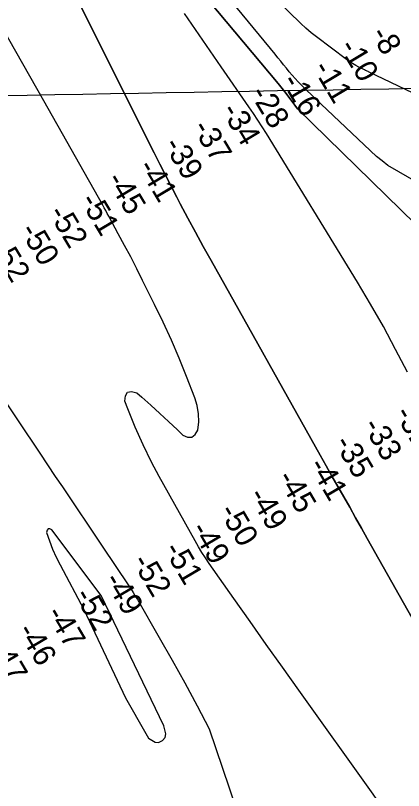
# Model space of a CAD drawing. Extents: x 3914892 to 3953151, y 242587 to 268572.
# Drawn here: x 3938431 to 3939590, y 258411 to 260725 of the extents above; entities that cross this region are included whole.
import ezdxf

# ---------------------------------------------------------------- set-up
doc = ezdxf.new("R2010")
doc.units = 0
for name, color, linetype in [('V-GRID-MAJR', 7, 'Continuous'), ('V-RIVR-RANG', 7, 'Continuous'), ('V-TOPO-DPTH', 7, 'Continuous'), ('V-TOPO-MAJR', 7, 'Continuous'), ('V-TOPO-MINR', 7, 'Continuous')]:
    doc.layers.add(name, color=color, linetype=linetype)

msp = doc.modelspace()

# ---------------------------------------------------------------- linework, layer by layer
at = {"layer": 'V-GRID-MAJR'}
msp.add_spline([(3918942.3880000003, 260140.297), (3924259.416, 260233.496), (3929576.431, 260327.467), (3934893.433, 260422.212), (3940210.42, 260517.73), (3945527.394, 260614.022), (3950844.353, 260711.087), (3950844.3540000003, 260711.087)], degree=3, dxfattribs=at)
at = {"layer": 'V-TOPO-DPTH'}
for points in [[(3937935.6033522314, 262362.5402043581), (3937946.807549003, 262343.63632242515), (3937958.257643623, 262324.87497740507), (3938066.361568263, 262151.54759992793), (3938132.132563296, 262046.2824872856), (3938198.016029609, 261941.08794122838), (3938264.0682028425, 261835.99924504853), (3938330.2328473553, 261730.98111545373), (3938533.302113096, 261409.237278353), (3938543.3552703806, 261393.41452513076), (3938553.4715195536, 261377.63248157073), (3938563.682406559, 261361.91150250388), (3938573.9563854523, 261346.23123309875), (3938689.531013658, 261170.99052217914), (3938725.5086589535, 261118.47567351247), (3938762.682482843, 261066.8546234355), (3938801.6505746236, 261016.5742712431), (3939215.8425195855, 260521.97311348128), (3939235.1154305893, 260496.93985141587), (3939254.337950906, 260471.8680751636), (3939273.484885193, 260446.73852763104), (3939890.5030939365, 259842.8503603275), (3939899.174331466, 259835.0878290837)], [(3937935.6033522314, 262362.5402043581), (3937946.807549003, 262343.63632242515), (3937958.257643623, 262324.87497740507), (3938066.361568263, 262151.54759992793), (3938132.132563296, 262046.2824872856), (3938198.016029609, 261941.08794122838), (3938264.0682028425, 261835.99924504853), (3938330.2328473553, 261730.98111545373), (3938533.302113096, 261409.237278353), (3938543.3552703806, 261393.41452513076), (3938553.4715195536, 261377.63248157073), (3938563.682406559, 261361.91150250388), (3938573.9563854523, 261346.23123309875), (3938689.531013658, 261170.99052217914), (3938725.5086589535, 261118.47567351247), (3938762.682482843, 261066.8546234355), (3938801.6505746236, 261016.5742712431), (3939215.8425195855, 260521.97311348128), (3939235.1154305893, 260496.93985141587), (3939254.337950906, 260471.8680751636), (3939273.484885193, 260446.73852763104), (3939890.5030939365, 259842.8503603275)], [(3940110.2800000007, 260258.01), (3939485.676288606, 260556.6594979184), (3939484.132907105, 260557.4550404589), (3939481.009910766, 260558.97150695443), (3939479.4302959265, 260559.69243090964), (3939476.273892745, 260561.1410262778), (3939473.154218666, 260562.6671138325), (3939456.795925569, 260570.9211261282), (3939447.215830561, 260576.0725193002), (3939437.834092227, 260581.54451440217), (3939428.749888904, 260587.49741239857), (3939419.864042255, 260593.77091232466), (3939329.7874783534, 260660.9505154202), (3939313.6231003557, 260673.72242143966), (3939297.9699429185, 260687.0614582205), (3939283.0836163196, 260701.25119114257), (3938621.524369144, 261346.29575137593)], [(3938618.811265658, 260766.56261342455), (3938669.4139997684, 260666.69985866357), (3938845.1139194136, 260314.8285701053), (3938861.841960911, 260281.58747193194), (3938878.7077570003, 260248.41695782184), (3938895.7801849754, 260215.35231980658), (3938912.9903675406, 260182.35826585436), (3938923.19890059, 260162.93525665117), (3938945.78941881, 260120.3764528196), (3938968.610226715, 260077.94271225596), (3938991.7764691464, 260035.69656659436), (3939015.1730012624, 259993.57548420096), (3939341.304889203, 259412.03733793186), (3939358.7805479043, 259380.94331128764), (3939376.294527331, 259349.87093091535), (3939393.8659878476, 259318.83101995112), (3939411.475769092, 259287.8127552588), (3939429.099378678, 259256.80227260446), (3939446.703105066, 259225.78051958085), (3939464.277006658, 259194.74186100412), (3939481.8310250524, 259163.69193205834), (3939832.9714719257, 258541.88976801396)], [(3939832.9714719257, 258541.88976801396), (3939481.8310250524, 259163.69193205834), (3939464.277006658, 259194.74186100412), (3939446.703105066, 259225.78051958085), (3939429.099378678, 259256.80227260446), (3939411.475769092, 259287.8127552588), (3939393.8659878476, 259318.83101995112), (3939376.294527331, 259349.87093091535), (3939358.7805479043, 259380.94331128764), (3939341.304889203, 259412.03733793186), (3939015.1730012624, 259993.57548420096), (3938991.7764691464, 260035.69656659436), (3938968.610226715, 260077.94271225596), (3938945.78941881, 260120.3764528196), (3938923.19890059, 260162.93525665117), (3938912.9903675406, 260182.35826585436), (3938895.7801849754, 260215.35231980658), (3938878.7077570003, 260248.41695782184), (3938861.841960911, 260281.58747193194), (3938845.1139194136, 260314.8285701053), (3938669.4139997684, 260666.69985866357), (3938618.811265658, 260766.56261342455)], [(3939601.6381155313, 259659.9443888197), (3939566.333453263, 259728.33550029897), (3939529.860262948, 259796.07768271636), (3939491.634280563, 259862.84647154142), (3939452.239770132, 259928.9663313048), (3939180.239102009, 260372.25024055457), (3939167.5819448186, 260392.49154555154), (3939154.699329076, 260412.5855989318), (3939141.478525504, 260432.45877488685), (3939128.0322633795, 260452.18469922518), (3939045.155761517, 260571.58248580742), (3938990.436754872, 260651.12227798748), (3938936.1639593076, 260730.96267019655)], [(3939601.6381155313, 259659.9443888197), (3939566.333453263, 259728.33550029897), (3939529.860262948, 259796.07768271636), (3939491.634280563, 259862.84647154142), (3939452.239770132, 259928.9663313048), (3939180.239102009, 260372.25024055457), (3939167.5819448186, 260392.49154555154), (3939154.699329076, 260412.5855989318), (3939141.478525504, 260432.45877488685), (3939128.0322633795, 260452.18469922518), (3939045.155761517, 260571.58248580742), (3938990.436754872, 260651.12227798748), (3938936.1639593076, 260730.96267019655)]]:
    msp.add_lwpolyline(points, dxfattribs=at)
at = {"layer": 'V-TOPO-MAJR'}
for points in [[(3937156.269427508, 261428.53489564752), (3937453.2876797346, 260966.50122927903), (3937472.1168183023, 260937.69377898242), (3937491.2337741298, 260909.08180549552), (3937510.7824558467, 260880.76304722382), (3937530.6189548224, 260852.63976576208), (3937558.444823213, 260813.8179744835), (3937564.5736847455, 260805.24468534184), (3937570.6883049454, 260796.66127767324), (3937576.7815631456, 260788.06269221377), (3937582.860580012, 260779.45398822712), (3937765.124393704, 260520.6617106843), (3937841.726175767, 260410.6274596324), (3937917.521368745, 260300.04678666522), (3937992.1066780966, 260188.64648082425), (3938065.885398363, 260076.69975306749), (3938185.2144720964, 259893.4722831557), (3938198.7665438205, 259872.7577901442), (3938212.375941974, 259852.081200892), (3938226.0713297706, 259831.46146727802), (3938239.824043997, 259810.87963742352), (3938503.3871171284, 259418.21284469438), (3938549.9439007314, 259348.8757536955), (3938571.0395051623, 259317.47317095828)], [(3938860.425784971, 259348.31562868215), (3938837.7064344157, 259391.1847869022), (3938811.985730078, 259443.28222197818), (3938788.536660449, 259496.44083846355), (3938766.6020139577, 259550.30690922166), (3938757.707172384, 259573.57669038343), (3938759.855632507, 259589.6301597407), (3938765.899635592, 259600.05765089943), (3938777.7869531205, 259602.04617475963), (3938793.5698136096, 259598.40872042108), (3938807.877687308, 259585.74117113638), (3938834.859888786, 259561.57294126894), (3938861.6532342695, 259537.19949830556), (3938888.1632957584, 259512.51823569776), (3938914.4845012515, 259487.63175999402), (3938930.348164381, 259472.45833441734), (3938944.812940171, 259466.63973720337), (3938957.5098283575, 259466.25864095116), (3938967.5548851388, 259474.03379614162), (3938975.832054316, 259487.24645229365), (3938978.190775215, 259511.88939042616), (3938977.875540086, 259536.27584210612), (3938973.549370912, 259560.2775641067), (3938966.5492457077, 259584.02279965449), (3938942.1379515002, 259646.92481518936), (3938920.03724425, 259701.57974120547), (3938896.9258587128, 259755.7868536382), (3938872.298455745, 259809.3222456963), (3938846.6603744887, 259862.40982417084), (3938810.7909182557, 259934.08914092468), (3938793.02657694, 259969.1359871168), (3938775.023010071, 260004.05793955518), (3938756.660604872, 260038.79255136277), (3938738.0589741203, 260073.40226941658), (3938709.392613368, 260126.08550586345), (3938704.92736018, 260134.25031730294), (3938700.438988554, 260142.40233587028), (3938695.915939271, 260150.53516512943), (3938691.3697715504, 260158.6552015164), (3938515.8024408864, 260470.68024022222), (3938453.367914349, 260581.2052821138), (3938390.6857312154, 260691.58913844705)], [(3939614.577538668, 258236.10234438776), (3939588.0782612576, 258274.08398232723), (3939565.9142396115, 258305.74567972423), (3939543.6840258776, 258337.36067821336), (3939521.354524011, 258368.90562834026), (3939498.9588300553, 258400.40387955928), (3939277.3866165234, 258710.99739000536), (3939228.7404504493, 258779.30502216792), (3939180.168081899, 258847.66500046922), (3939131.7064096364, 258916.10349797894), (3939083.318534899, 258984.59434162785), (3939009.467728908, 259089.30650482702), (3938998.3255826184, 259105.64724240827), (3938987.535923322, 259122.2097544), (3938977.2749945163, 259139.10492800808), (3938967.366552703, 259156.22187602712), (3938860.425784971, 259348.31562868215)], [(3938571.0395051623, 259317.47317095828), (3938689.7224621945, 259140.93720064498), (3938769.3700368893, 259022.56052408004), (3938776.0595267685, 259012.38790220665), (3938782.603559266, 259002.12467983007), (3938788.9294056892, 258991.72555669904), (3938795.109794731, 258981.2358330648), (3938860.334162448, 258867.81112636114), (3938898.598820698, 258800.3115460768), (3938936.3053959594, 258732.50609600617), (3938973.1748467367, 258664.2418412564), (3939009.4862145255, 258595.67171672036), (3939149.9565761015, 258181.67266925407), (3939175.0078269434, 258106.98229834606), (3939196.699380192, 258072.10815225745), (3939215.7444061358, 258038.37666572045), (3939228.2127662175, 258005.11300591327), (3939240.632293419, 257973.6979149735), (3939265.2591513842, 257922.7279221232)], [(3938858.3977390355, 258554.4576324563), (3938869.9701063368, 258560.66903050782), (3938877.5496051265, 258569.84386610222), (3938879.9452261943, 258580.21727256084), (3938874.3456166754, 258604.65213213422), (3938686.6093863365, 258993.60704358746), (3938539.94785229, 259189.9237409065), (3938533.548570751, 259192.6031089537), (3938528.521485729, 259192.58798657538), (3938525.55269548, 259188.53112855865), (3938523.9561017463, 259181.7797801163), (3938532.458711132, 259156.81874631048), (3938541.8637990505, 259132.23205484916), (3938552.622604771, 259108.20687690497), (3938564.2838890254, 259084.55604130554), (3938634.709677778, 258951.22442656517), (3938759.28407351, 258687.8205079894), (3938820.4184974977, 258581.22884217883), (3938827.9633918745, 258567.83024335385), (3938848.129169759, 258555.1129910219), (3938858.3977390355, 258554.4576324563)]]:
    msp.add_lwpolyline(points, dxfattribs=at)
at = {"layer": 'V-TOPO-MINR'}
for points in [[(3939890.5030939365, 259842.8503603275), (3939273.484885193, 260446.73852763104), (3939254.337950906, 260471.8680751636), (3939235.1154305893, 260496.93985141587), (3939215.8425195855, 260521.97311348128), (3938801.6505746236, 261016.5742712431), (3938762.682482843, 261066.8546234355), (3938725.5086589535, 261118.47567351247), (3938689.531013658, 261170.99052217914), (3938573.9563854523, 261346.23123309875), (3938563.682406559, 261361.91150250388), (3938553.4715195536, 261377.63248157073), (3938543.3552703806, 261393.41452513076), (3938533.302113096, 261409.237278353), (3938330.2328473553, 261730.98111545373), (3938264.0682028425, 261835.99924504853), (3938198.016029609, 261941.08794122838), (3938132.132563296, 262046.2824872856), (3938066.361568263, 262151.54759992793), (3937958.257643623, 262324.87497740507), (3937946.807549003, 262343.63632242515), (3937935.6033522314, 262362.5402043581)], [(3939974.735562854, 260028.50245078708), (3939542.998862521, 260277.52856744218), (3939526.027029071, 260290.6526518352), (3939509.3912935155, 260304.17514412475), (3939325.3222215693, 260477.86481799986), (3939313.681306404, 260489.09272007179), (3939302.128373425, 260500.40940562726), (3939290.707413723, 260511.85926640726), (3939279.3744362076, 260523.3979106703), (3939275.5463907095, 260527.3408903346), (3939266.339317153, 260537.10321152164), (3939257.326365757, 260547.0366120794), (3939248.6045975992, 260557.22663169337), (3939240.0769516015, 260567.5877306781), (3939231.691240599, 260578.07423249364), (3939223.300277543, 260588.55652685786), (3939214.901436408, 260599.0325100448), (3939206.497343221, 260609.5042857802), (3938573.7346600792, 261377.8323928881)], [(3940110.2800000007, 260258.01), (3939485.676288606, 260556.6594979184), (3939484.132907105, 260557.4550404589), (3939481.009910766, 260558.97150695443), (3939479.4302959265, 260559.69243090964), (3939476.273892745, 260561.1410262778), (3939473.154218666, 260562.6671138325), (3939456.795925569, 260570.9211261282), (3939447.215830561, 260576.0725193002), (3939437.834092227, 260581.54451440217), (3939428.749888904, 260587.49741239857), (3939419.864042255, 260593.77091232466), (3939329.7874783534, 260660.9505154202), (3939313.6231003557, 260673.72242143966), (3939297.9699429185, 260687.0614582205), (3939283.0836163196, 260701.25119114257), (3938621.524369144, 261346.29575137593)], [(3939832.9714719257, 258541.88976801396), (3939481.8310250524, 259163.69193205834), (3939464.277006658, 259194.74186100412), (3939446.703105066, 259225.78051958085), (3939429.099378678, 259256.80227260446), (3939411.475769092, 259287.8127552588), (3939393.8659878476, 259318.83101995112), (3939376.294527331, 259349.87093091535), (3939358.7805479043, 259380.94331128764), (3939341.304889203, 259412.03733793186), (3939015.1730012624, 259993.57548420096), (3938991.7764691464, 260035.69656659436), (3938968.610226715, 260077.94271225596), (3938945.78941881, 260120.3764528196), (3938923.19890059, 260162.93525665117), (3938912.9903675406, 260182.35826585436), (3938895.7801849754, 260215.35231980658), (3938878.7077570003, 260248.41695782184), (3938861.841960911, 260281.58747193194), (3938845.1139194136, 260314.8285701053), (3938669.4139997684, 260666.69985866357), (3938618.811265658, 260766.56261342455)], [(3939601.6381155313, 259659.9443888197), (3939566.333453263, 259728.33550029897), (3939529.860262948, 259796.07768271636), (3939491.634280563, 259862.84647154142), (3939452.239770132, 259928.9663313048), (3939180.239102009, 260372.25024055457), (3939167.5819448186, 260392.49154555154), (3939154.699329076, 260412.5855989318), (3939141.478525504, 260432.45877488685), (3939128.0322633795, 260452.18469922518), (3939045.155761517, 260571.58248580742), (3938990.436754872, 260651.12227798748), (3938936.1639593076, 260730.96267019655)]]:
    msp.add_lwpolyline(points, dxfattribs=at)

# ---------------------------------------------------------------- texts
at = {"layer": 'V-RIVR-RANG'}
for s, height, rotation, p in [('-8', 67, 300.88811111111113, (3939489.596878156, 260669.74389619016)), ('-10', 67, 300.88811111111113, (3939395.6634108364, 260631.97561166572)), ('-11', 67, 300.88811111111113, (3939317.302634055, 260568.17500036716)), ('-16', 67, 300.88811111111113, (3939224.181654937, 260529.0485074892)), ('-28', 67, 300.88811111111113, (3939129.3012847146, 260492.86479937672)), ('-34', 67, 300.88811111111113, (3939043.4926994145, 260441.5144313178)), ('-37', 67, 300.88811111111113, (3938957.2718066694, 260390.853303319)), ('-39', 67, 300.88811111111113, (3938871.604699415, 260339.2664313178)), ('-41', 67, 300.88811111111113, (3938794.5990696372, 260273.20113943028)), ('-45', 67, 300.88811111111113, (3938700.665602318, 260235.4328549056)), ('-51', 67, 300.88811111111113, (3938621.6277520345, 260172.76408390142)), ('-52', 67, 300.88811111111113, (3938527.1526259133, 260135.9012716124)), ('-50', 67, 300.88811111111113, (3938442.1565288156, 260083.1926952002)), ('-52', 67, 300.88811111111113, (3938355.265625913, 260033.65327161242)), ('-31', 67.00000000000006, 300.50005555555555, (3939561.4207995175, 259537.07967764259)), ('-33', 67.00000000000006, 300.50005555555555, (3939466.4307002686, 259501.31187784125)), ('-35', 67.00000000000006, 300.50005555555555, (3939380.945970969, 259449.40719782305)), ('-41', 67.00000000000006, 300.50005555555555, (3939304.4300978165, 259382.2747575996)), ('-45', 67.00000000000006, 300.50005555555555, (3939210.243269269, 259345.1432777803)), ('-49', 67.00000000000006, 300.50005555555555, (3939124.892418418, 259293.0123177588)), ('-50', 67.00000000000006, 300.50005555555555, (3939036.9978770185, 259245.19867779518)), ('-49', 67.00000000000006, 300.50005555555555, (3938952.3164184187, 259191.93031775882)), ('-51', 67.00000000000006, 300.50005555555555, (3938871.9190702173, 259131.38899762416)), ('-52', 67.00000000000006, 300.50005555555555, (3938777.196727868, 259095.1666378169)), ('-49', 67.00000000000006, 300.50005555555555, (3938693.4524184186, 259040.3073177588)), ('-52', 67.00000000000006, 300.50005555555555, (3938604.6207278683, 258994.0856378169)), ('-47', 67.00000000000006, 300.50005555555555, (3938520.602666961, 258939.69105448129)), ('-46', 67.00000000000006, 300.50005555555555, (3938434.454539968, 258888.91259776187)), ('-47', 67.00000000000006, 300.50005555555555, (3938348.0266669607, 258838.60905448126))]:
    msp.add_text(s, height=height, rotation=rotation, dxfattribs=at).set_placement(p)

doc.saveas('drawing.dxf')
